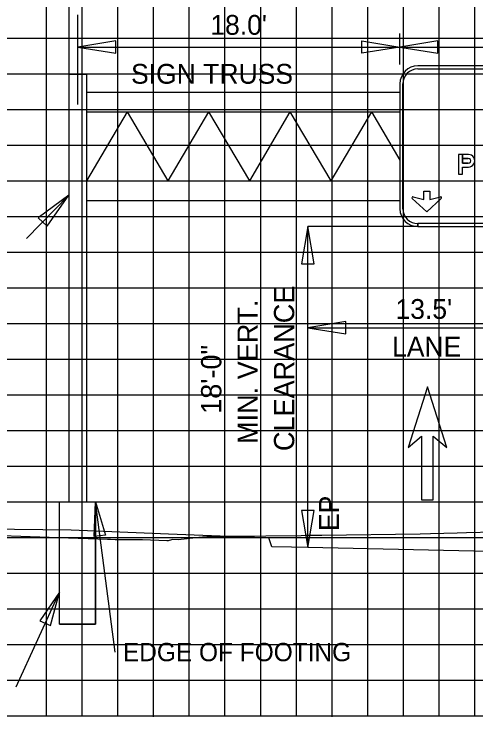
# Model space of a CAD drawing. Extents: x 2193008 to 2198143, y 1236112 to 1237864.
# Drawn here: x 2194935.04 to 2194960.92, y 1237258.05 to 1237297.45 of the extents above; entities that cross this region are included whole.
import ezdxf

# ---------------------------------------------------------------- set-up
doc = ezdxf.new("R2010")
doc.units = 0
for name, color, linetype in [('3', 7, 'Continuous'), ('60', 7, 'Continuous'), ('CL-CNST', 7, 'Continuous'), ('GSBWFILL', 7, 'Continuous'), ('GSCOLORFILL', 7, 'Continuous'), ('GSDIMS', 7, 'Continuous'), ('GSOUTLINE', 7, 'Continuous'), ('Level 28', 7, 'Continuous'), ('Level 55', 7, 'Continuous'), ('Level 62', 7, 'Continuous'), ('M-ROADS', 7, 'Continuous'), ('V7Level1', 7, 'Continuous')]:
    doc.layers.add(name, color=color, linetype=linetype)

msp = doc.modelspace()

# ---------------------------------------------------------------- linework, layer by layer
msp.add_line((2194938.61, 1237292.389), (2194938.61, 1237297.403))
at = {"layer": '3'}
for p, q in [((2194938.11, 1237306.728), (2194938.11, 1237294.084)), ((2194938.11, 1237294.084), (2194938.11, 1237270.106)), ((2194939.11, 1237294.084), (2194939.11, 1237270.106)), ((2194935.741, 1237284.863), (2194938.11, 1237287.306)), ((2194951.493, 1237267.538), (2194951.493, 1237285.538)), ((2194937.586, 1237270.106), (2194939.61, 1237270.106)), ((2194937.586, 1237263.254), (2194937.586, 1237270.106)), ((2194939.61, 1237263.254), (2194939.61, 1237270.106)), ((2194940.702, 1237261.681), (2194939.61, 1237270.106)), ((2194935.16, 1237259.743), (2194937.586, 1237265.045)), ((2194937.586, 1237263.254), (2194939.61, 1237263.254))]:
    msp.add_line(p, q, dxfattribs=at)
at = {"layer": '60'}
for p, q in [((2194892.86, 1237258.106), (2195022.86, 1237258.106)), ((2194942.86, 1237258.046), (2194942.86, 1237258.106)), ((2194952.86, 1237258.046), (2194952.86, 1237258.106))]:
    msp.add_line(p, q, dxfattribs=at)
at = {"layer": 'CL-CNST'}
msp.add_lwpolyline([(2195022.86, 1237269.861), (2195014.414, 1237267.045), (2195010.113, 1237266.873), (2195006.414, 1237266.725), (2195006.088, 1237266.725), (2195006.085, 1237266.725), (2195005.918, 1237266.225), (2195004.805, 1237266.314), (2195003.918, 1237266.385), (2194951.493, 1237267.538), (2194950.59, 1237267.558), (2194949.493, 1237267.582), (2194949.323, 1237268.082), (2194948.993, 1237268.082), (2194943.692, 1237268.294), (2194938.236, 1237268.512), (2194935.061, 1237268.561), (2194927.574, 1237268.677)], dxfattribs=at)
at = {"layer": 'GSBWFILL'}
for points in [[(2194959.952, 1237289.582), (2194959.952, 1237288.474), (2194960.171, 1237288.474), (2194960.171, 1237288.872), (2194960.5, 1237288.872)], [(2194960.488, 1237289.093), (2194960.171, 1237289.093), (2194960.171, 1237289.582), (2194959.952, 1237289.582)], [(2194960.5, 1237289.582), (2194960.171, 1237289.582), (2194960.171, 1237289.36), (2194960.488, 1237289.36)], [(2194957.397, 1237287.203), (2194957.996, 1237287.05), (2194957.996, 1237287.516), (2194958.333, 1237287.516), (2194958.333, 1237287.05), (2194958.932, 1237287.203)], [(2194958.979, 1237287.116), (2194958.165, 1237286.375), (2194957.35, 1237287.116)]]:
    msp.add_lwpolyline(points, dxfattribs=at)
for centre, start, end in [((2194957.385, 1237287.154), 75.5925, 227.6952), ((2194958.945, 1237287.154), 312.3048, 104.4075)]:
    msp.add_arc(centre, 0.0511, start, end, dxfattribs=at)
for centre, major_axis, start_param, end_param in [((2194960.499, 1237289.227), (0, 0.134), 3.056611, 6.368167), ((2194960.5, 1237289.227), (0, 0.355), 3.140988, 6.28379)]:
    msp.add_ellipse(centre, major_axis=major_axis, ratio=0.98587, start_param=start_param, end_param=end_param, dxfattribs=at)
at = {"layer": 'GSCOLORFILL'}
for p, q in [((2194985.672, 1237294.547), (2194957.664, 1237294.547)), ((2194957.664, 1237294.38), (2194985.672, 1237294.38)), ((2194956.664, 1237293.547), (2194956.664, 1237286.538)), ((2194956.831, 1237286.538), (2194956.831, 1237293.547)), ((2194957.664, 1237285.538), (2194957.664, 1237285.705)), ((2194985.672, 1237285.705), (2194957.666, 1237285.705)), ((2194957.666, 1237285.705), (2194957.666, 1237285.538)), ((2194957.666, 1237285.538), (2194985.672, 1237285.538))]:
    msp.add_line(p, q, dxfattribs=at)
for points in [[(2194959.952, 1237289.582), (2194959.952, 1237288.474), (2194960.171, 1237288.474), (2194960.171, 1237288.872), (2194960.5, 1237288.872)], [(2194960.488, 1237289.093), (2194960.171, 1237289.093), (2194960.171, 1237289.582), (2194959.952, 1237289.582)], [(2194960.5, 1237289.582), (2194960.171, 1237289.582), (2194960.171, 1237289.36), (2194960.488, 1237289.36)], [(2194957.397, 1237287.203), (2194957.996, 1237287.05), (2194957.996, 1237287.516), (2194958.333, 1237287.516), (2194958.333, 1237287.05), (2194958.932, 1237287.203)], [(2194958.979, 1237287.116), (2194958.165, 1237286.375), (2194957.35, 1237287.116)]]:
    msp.add_lwpolyline(points, dxfattribs=at)
for centre, radius, start, end in [((2194957.664, 1237293.547), 1, 90, 180), ((2194957.664, 1237293.547), 0.833, 90, 180), ((2194957.385, 1237287.154), 0.0511, 75.5925, 227.6952), ((2194958.945, 1237287.154), 0.0511, 312.3048, 104.4075), ((2194957.664, 1237286.538), 1, 180, 270), ((2194957.664, 1237286.538), 0.833, 180, 270)]:
    msp.add_arc(centre, radius, start, end, dxfattribs=at)
for centre, major_axis, start_param, end_param in [((2194960.499, 1237289.227), (0, 0.134), 3.056611, 6.368167), ((2194960.5, 1237289.227), (0, 0.355), 3.140988, 6.28379)]:
    msp.add_ellipse(centre, major_axis=major_axis, ratio=0.98587, start_param=start_param, end_param=end_param, dxfattribs=at)
at = {"layer": 'GSDIMS'}
for p, q in [((2194956.664, 1237294.621), (2194956.664, 1237296.362)), ((2194938.61, 1237295.604), (2194956.664, 1237295.604)), ((2194956.664, 1237295.604), (2194986.672, 1237295.604)), ((2194938.11, 1237294.084), (2194939.11, 1237294.084)), ((2194939.11, 1237293.084), (2194956.664, 1237293.084)), ((2194941.389, 1237291.974), (2194939.11, 1237288.111)), ((2194939.11, 1237291.974), (2194956.664, 1237291.974)), ((2194941.389, 1237291.974), (2194943.667, 1237288.111)), ((2194945.946, 1237291.974), (2194943.667, 1237288.111)), ((2194945.946, 1237291.974), (2194948.225, 1237288.111)), ((2194950.503, 1237291.974), (2194948.225, 1237288.111)), ((2194950.503, 1237291.974), (2194952.782, 1237288.111)), ((2194955.06, 1237291.974), (2194952.782, 1237288.111)), ((2194955.06, 1237291.974), (2194956.664, 1237289.255)), ((2194939.11, 1237288.111), (2194956.664, 1237288.111)), ((2194939.11, 1237287.001), (2194956.664, 1237287.001)), ((2194957.666, 1237285.538), (2194951.493, 1237285.538)), ((2194951.493, 1237279.864), (2194964.918, 1237279.864))]:
    msp.add_line(p, q, dxfattribs=at)
for points in [[(2194938.61, 1237295.604), (2194940.739, 1237295.257), (2194940.739, 1237295.952)], [(2194956.664, 1237295.604), (2194954.535, 1237295.257), (2194954.535, 1237295.952)], [(2194956.664, 1237295.604), (2194958.792, 1237295.257), (2194958.792, 1237295.952)], [(2194938.11, 1237287.306), (2194936.388, 1237286.034), (2194936.902, 1237285.556)], [(2194951.493, 1237285.538), (2194951.139, 1237283.455), (2194951.848, 1237283.455)], [(2194951.493, 1237279.864), (2194953.622, 1237279.517), (2194953.622, 1237280.211)], [(2194939.61, 1237270.106), (2194940.175, 1237268.241), (2194939.54, 1237268.159)], [(2194951.493, 1237267.538), (2194951.848, 1237269.621), (2194951.139, 1237269.621)], [(2194937.586, 1237265.045), (2194936.495, 1237263.431), (2194937.077, 1237263.164)]]:
    msp.add_lwpolyline(points, close=True, dxfattribs=at)
at = {"layer": 'GSOUTLINE'}
for p, q in [((2194960.171, 1237289.093), (2194960.488, 1237289.093)), ((2194960.171, 1237288.872), (2194960.5, 1237288.872))]:
    msp.add_line(p, q, dxfattribs=at)
for points in [[(2194960.5, 1237289.582), (2194959.952, 1237289.582), (2194959.952, 1237288.474), (2194960.171, 1237288.474), (2194960.171, 1237288.872)], [(2194960.488, 1237289.36), (2194960.171, 1237289.36), (2194960.171, 1237289.093)], [(2194957.397, 1237287.203), (2194957.996, 1237287.05), (2194957.996, 1237287.516), (2194958.333, 1237287.516), (2194958.333, 1237287.05), (2194958.932, 1237287.203)], [(2194958.979, 1237287.116), (2194958.165, 1237286.375), (2194957.35, 1237287.116)]]:
    msp.add_lwpolyline(points, dxfattribs=at)
for centre, start, end in [((2194957.385, 1237287.154), 75.5925, 227.6952), ((2194958.945, 1237287.154), 312.3048, 104.4075)]:
    msp.add_arc(centre, 0.0511, start, end, dxfattribs=at)
for centre, major_axis, start_param, end_param in [((2194960.499, 1237289.227), (0, 0.134), 3.056611, 6.368167), ((2194960.5, 1237289.227), (0, 0.355), 3.140988, 6.28379)]:
    msp.add_ellipse(centre, major_axis=major_axis, ratio=0.98587, start_param=start_param, end_param=end_param, dxfattribs=at)
at = {"layer": 'Level 28'}
for p, q in [((2194958.206, 1237276.554), (2194957.117, 1237273.156)), ((2194959.295, 1237273.156), (2194958.206, 1237276.554)), ((2194957.117, 1237273.156), (2194957.879, 1237273.796)), ((2194957.879, 1237273.796), (2194957.879, 1237270.225)), ((2194958.533, 1237270.225), (2194958.533, 1237273.796)), ((2194958.533, 1237273.796), (2194959.295, 1237273.156)), ((2194957.879, 1237270.225), (2194958.533, 1237270.225))]:
    msp.add_line(p, q, dxfattribs=at)
at = {"layer": 'Level 62'}
for p, q in [((2194936.86, 1237258.106), (2194936.86, 1237318.106)), ((2194938.86, 1237258.106), (2194938.86, 1237318.106)), ((2194940.86, 1237258.106), (2194940.86, 1237318.106)), ((2194942.86, 1237258.106), (2194942.86, 1237318.106)), ((2194944.86, 1237258.106), (2194944.86, 1237318.106)), ((2194946.86, 1237258.106), (2194946.86, 1237318.106)), ((2194948.86, 1237258.106), (2194948.86, 1237318.106)), ((2194950.86, 1237258.106), (2194950.86, 1237318.106)), ((2194952.86, 1237258.106), (2194952.86, 1237318.106)), ((2194954.86, 1237258.106), (2194954.86, 1237318.106)), ((2194956.86, 1237258.106), (2194956.86, 1237318.106)), ((2194958.86, 1237258.106), (2194958.86, 1237318.106)), ((2194960.86, 1237258.106), (2194960.86, 1237318.106)), ((2194892.86, 1237296.106), (2195022.86, 1237296.106)), ((2194892.86, 1237294.106), (2195022.86, 1237294.106)), ((2194892.86, 1237292.106), (2195022.86, 1237292.106)), ((2194892.86, 1237290.106), (2195022.86, 1237290.106)), ((2194892.86, 1237288.106), (2195022.86, 1237288.106)), ((2194892.86, 1237286.106), (2195022.86, 1237286.106)), ((2194892.86, 1237284.106), (2195022.86, 1237284.106)), ((2194892.86, 1237282.106), (2195022.86, 1237282.106)), ((2194892.86, 1237280.106), (2195022.86, 1237280.106)), ((2194892.86, 1237278.106), (2195022.86, 1237278.106)), ((2194892.86, 1237276.106), (2195022.86, 1237276.106)), ((2194892.86, 1237274.106), (2195022.86, 1237274.106)), ((2194892.86, 1237272.106), (2195022.86, 1237272.106)), ((2194892.86, 1237270.106), (2195022.86, 1237270.106)), ((2194892.86, 1237268.106), (2195022.86, 1237268.106)), ((2194892.86, 1237266.106), (2195022.86, 1237266.106)), ((2194892.86, 1237264.106), (2195022.86, 1237264.106)), ((2194892.86, 1237262.106), (2195022.86, 1237262.106)), ((2194892.86, 1237260.106), (2195022.86, 1237260.106)), ((2194892.86, 1237258.106), (2195022.86, 1237258.106))]:
    msp.add_line(p, q, dxfattribs=at)
at = {"layer": 'M-ROADS'}
msp.add_lwpolyline([(2194961.933, 1237268.413), (2194960.388, 1237268.369), (2194959.863, 1237268.354), (2194958.383, 1237268.312), (2194957.792, 1237268.294), (2194952.286, 1237268.226), (2194951.901, 1237268.224), (2194951.667, 1237268.217), (2194951.628, 1237268.215), (2194951.411, 1237268.211), (2194951.13, 1237268.206), (2194947.163, 1237268.167), (2194946.883, 1237268.165), (2194945.858, 1237268.143), (2194945.839, 1237268.142), (2194945.592, 1237268.124), (2194945.393, 1237268.101), (2194944.241, 1237267.983), (2194943.941, 1237267.986), (2194943.726, 1237267.945), (2194943.672, 1237267.918), (2194943.669, 1237267.917), (2194943.669, 1237267.916), (2194943.667, 1237267.916), (2194943.631, 1237267.917), (2194943.596, 1237267.919), (2194942.243, 1237267.977), (2194942.194, 1237267.976), (2194940.701, 1237267.984), (2194940.444, 1237267.986), (2194940.27, 1237267.987), (2194937.552, 1237268.087), (2194932.211, 1237268.281)], dxfattribs=at)
at = {"layer": 'V7Level1'}
msp.add_lwpolyline([(2194939.61, 1237263.254), (2194937.586, 1237263.254), (2194937.586, 1237270.106), (2194939.61, 1237270.106)], close=True, dxfattribs=at)

# ---------------------------------------------------------------- texts
at = {"layer": 'Level 55'}
for s, height, p in [("18.0'", 1.1105, (2194946.038, 1237296.293)), ('SIGN TRUSS', 1.1105, (2194941.597, 1237293.548)), ("13.5'", 1.1105, (2194956.413, 1237280.364)), ('LANE', 1.1105, (2194956.22, 1237278.254)), ('EDGE OF FOOTING', 1.02464, (2194941.141, 1237261.171))]:
    msp.add_text(s, height=height, dxfattribs=at).set_placement(p)
for s, height, p in [('CLEARANCE', 1.1346, (2194950.74, 1237272.952)), ('MIN. VERT.', 1.1346, (2194948.698, 1237273.352)), ('18\'-0"', 1.1346, (2194946.656, 1237275.04)), ('EP', 1.1105, (2194953.244, 1237268.47))]:
    msp.add_text(s, height=height, rotation=90, dxfattribs=at).set_placement(p)

doc.saveas('drawing.dxf')
